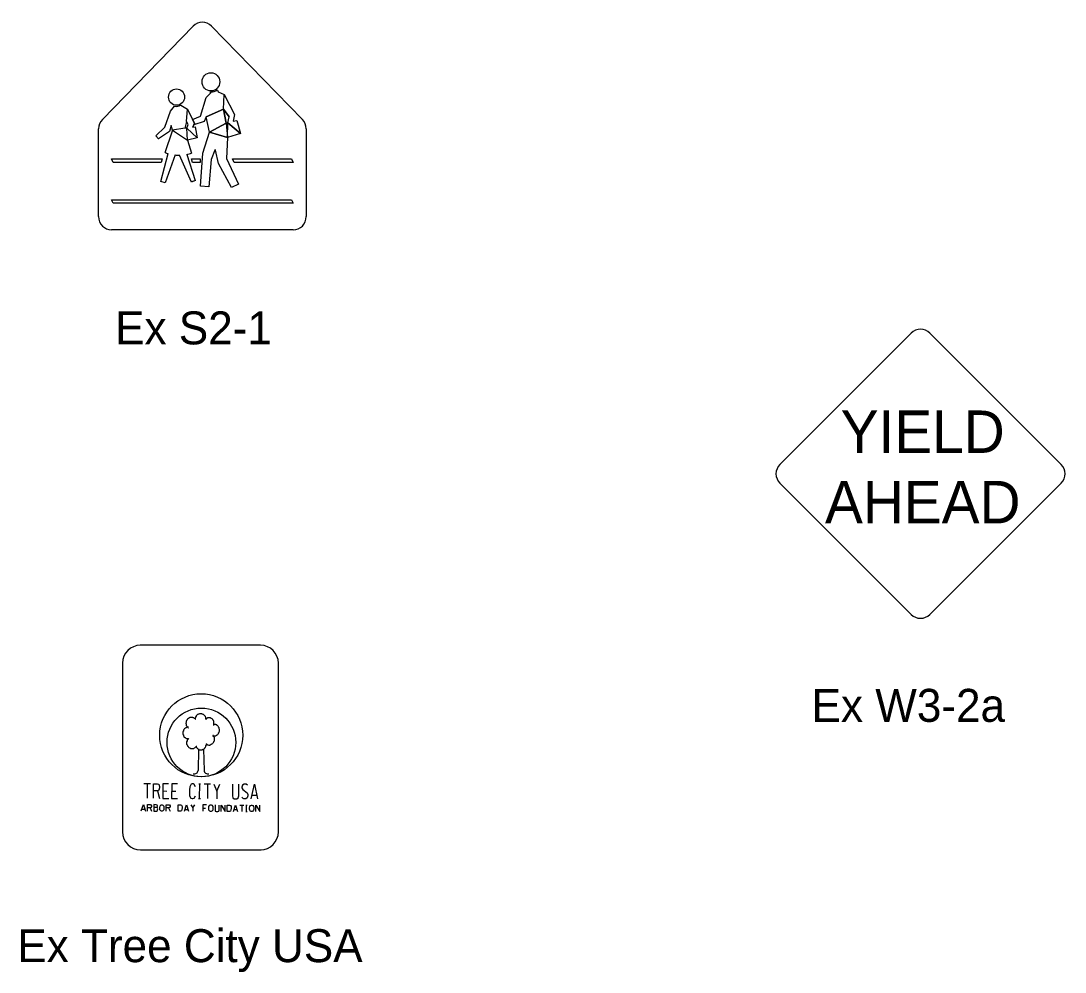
# Model space of a CAD drawing. Extents: x 42133 to 45533, y 41351 to 47951.
# Drawn here: x 43037.9 to 43275.5, y 46096.8 to 46313.2 of the extents above; entities that cross this region are included whole.
import ezdxf

# ---------------------------------------------------------------- set-up
doc = ezdxf.new("R2010")
doc.units = 0
doc.layers.add('P_TRAF_SIGN_SignDetails', color=7, linetype='Continuous')

msp = doc.modelspace()

# ---------------------------------------------------------------- linework, layer by layer
at = {"layer": 'P_TRAF_SIGN_SignDetails'}
for p, q in [((43056.47, 46290.82), (43077.12, 46312.05)), ((43081.31, 46312.05), (43101.97, 46290.82)), ((43082.56, 46297.55), (43082.65, 46297.49)), ((43078.78, 46291.58), (43080.06, 46295.78)), ((43080.06, 46295.78), (43081.05, 46296.76)), ((43081.07, 46297.06), (43081.05, 46296.76)), ((43081.05, 46296.76), (43081.07, 46297.06)), ((43082.65, 46297.49), (43082.78, 46297.06)), ((43082.78, 46297.06), (43084.14, 46296.52)), ((43084.04, 46293.17), (43084.14, 46296.52)), ((43084.14, 46296.52), (43086.48, 46291.93)), ((43071.92, 46292.73), (43072.87, 46293.83)), ((43071.92, 46292.73), (43072.87, 46293.83)), ((43074.29, 46294.03), (43075.83, 46293.16)), ((43074.29, 46294.03), (43075.83, 46293.16)), ((43075.56, 46290.37), (43075.83, 46293.16)), ((43077.39, 46289.95), (43075.83, 46293.16)), ((43077.39, 46289.95), (43075.83, 46293.16)), ((43075.83, 46293.16), (43077.39, 46289.95)), ((43075.83, 46293.16), (43077.39, 46289.95)), ((43075.9, 46293), (43075.9, 46293)), ((43084.04, 46293.17), (43080.09, 46291.38)), ((43080.09, 46291.38), (43084.04, 46293.17)), ((43085.27, 46291.39), (43084.04, 46293.17)), ((43084.61, 46289.95), (43084.04, 46293.17)), ((43084.04, 46293.17), (43085.27, 46291.39)), ((43085.27, 46291.39), (43084.04, 46293.17)), ((43084.04, 46293.17), (43084.61, 46289.95)), ((43085.27, 46291.39), (43084.04, 46293.17)), ((43084.04, 46293.17), (43084.61, 46289.95)), ((43070.7, 46289.06), (43071.92, 46292.73)), ((43070.7, 46289.06), (43071.92, 46292.73)), ((43075.56, 46290.37), (43075.19, 46288.82)), ((43075.96, 46289.69), (43075.56, 46290.37)), ((43076.06, 46292.67), (43076.06, 46292.67)), ((43076.23, 46292.33), (43076.23, 46292.33)), ((43076.39, 46292), (43076.39, 46292)), ((43076.55, 46291.66), (43076.55, 46291.66)), ((43076.72, 46291.33), (43076.72, 46291.33)), ((43076.88, 46290.99), (43076.88, 46290.99)), ((43076.99, 46290.77), (43078.78, 46291.58)), ((43080.09, 46291.38), (43079.59, 46290.34)), ((43080.81, 46287.92), (43080.09, 46291.38)), ((43084.97, 46290.04), (43085.27, 46291.39)), ((43084.97, 46290.04), (43085.27, 46291.39)), ((43086.48, 46291.93), (43086.22, 46290.43)), ((43086.22, 46290.43), (43087.01, 46290.59)), ((43087.01, 46290.59), (43087.88, 46287.59)), ((43055.59, 46268.7), (43055.59, 46288.68)), ((43068.62, 46287.09), (43070.7, 46289.06)), ((43068.62, 46287.09), (43070.7, 46289.06)), ((43071.71, 46288.06), (43069.23, 46286.42)), ((43071.71, 46288.06), (43069.23, 46286.42)), ((43070.76, 46283.29), (43072.37, 46288.18)), ((43070.76, 46283.29), (43072.37, 46288.18)), ((43072.09, 46289.46), (43071.71, 46288.06)), ((43072.09, 46289.46), (43071.71, 46288.06)), ((43072.39, 46288.36), (43072.09, 46289.46)), ((43072.39, 46288.36), (43072.09, 46289.46)), ((43072.37, 46288.18), (43072.39, 46288.36)), ((43072.37, 46288.18), (43072.39, 46288.36)), ((43075.19, 46288.82), (43072.39, 46288.36)), ((43075.19, 46288.82), (43072.39, 46288.36)), ((43072.39, 46288.36), (43075.81, 46286.12)), ((43072.39, 46288.36), (43075.81, 46286.12)), ((43075.64, 46288.84), (43075.19, 46288.82)), ((43075.64, 46288.84), (43075.96, 46289.69)), ((43078.01, 46286.65), (43075.64, 46288.84)), ((43075.81, 46286.12), (43075.64, 46288.84)), ((43075.64, 46288.84), (43078.01, 46286.65)), ((43077.39, 46289.95), (43077.07, 46289.02)), ((43077.07, 46289.02), (43077.39, 46289.95)), ((43077.39, 46289.95), (43077.07, 46289.02)), ((43077.39, 46289.95), (43077.07, 46289.02)), ((43077.07, 46289.02), (43077.55, 46289.11)), ((43077.07, 46289.02), (43077.55, 46289.11)), ((43079.59, 46290.34), (43077.25, 46289.56)), ((43077.28, 46289.65), (43077.28, 46289.65)), ((43077.28, 46289.65), (43077.28, 46289.65)), ((43077.55, 46289.11), (43078.01, 46286.65)), ((43077.55, 46289.11), (43078.01, 46286.65)), ((43084.61, 46289.95), (43080.81, 46287.92)), ((43084.97, 46290.04), (43084.61, 46289.95)), ((43084.61, 46289.95), (43084.95, 46286.73)), ((43084.95, 46286.73), (43084.97, 46290.04)), ((43084.95, 46286.73), (43084.97, 46290.04)), ((43087.88, 46287.59), (43084.97, 46290.04)), ((43084.97, 46290.04), (43087.88, 46287.59)), ((43102.82, 46288.68), (43102.82, 46268.7)), ((43069.23, 46286.42), (43068.62, 46287.09)), ((43069.23, 46286.42), (43068.62, 46287.09)), ((43069.17, 46286.49), (43069.33, 46286.49)), ((43078.01, 46286.65), (43075.81, 46286.12)), ((43078.01, 46286.65), (43075.81, 46286.12)), ((43075.81, 46286.12), (43076.76, 46283.13)), ((43075.81, 46286.12), (43076.76, 46283.13)), ((43079.28, 46283.13), (43080.81, 46287.92)), ((43084.95, 46286.73), (43080.81, 46287.92)), ((43080.81, 46287.92), (43084.95, 46286.73)), ((43080.81, 46287.92), (43084.95, 46286.73)), ((43084.95, 46286.73), (43080.81, 46287.92)), ((43084.95, 46286.73), (43080.81, 46287.92)), ((43080.81, 46287.92), (43084.95, 46286.73)), ((43080.81, 46287.92), (43084.95, 46286.73)), ((43084.95, 46286.73), (43080.81, 46287.92)), ((43084.95, 46286.73), (43080.81, 46287.92)), ((43080.81, 46287.92), (43084.95, 46286.73)), ((43084.95, 46286.73), (43084.71, 46281.9)), ((43087.88, 46287.59), (43084.95, 46286.73)), ((43082.02, 46283.83), (43081.21, 46281.73)), ((43082.89, 46280.79), (43082.18, 46283.83)), ((43058.55, 46281.85), (43070.06, 46281.85)), ((43058.93, 46281.04), (43058.55, 46281.85)), ((43069.86, 46281.04), (43058.93, 46281.04)), ((43069.78, 46276.68), (43071.4, 46283.03)), ((43069.78, 46276.68), (43071.4, 46283.03)), ((43070.06, 46281.85), (43069.86, 46281.04)), ((43073, 46282.74), (43070.72, 46276.39)), ((43073, 46282.74), (43070.72, 46276.39)), ((43076.72, 46276.54), (43074.01, 46282.69)), ((43076.72, 46276.54), (43074.01, 46282.69)), ((43075.65, 46282.86), (43077.58, 46276.88)), ((43075.65, 46282.86), (43077.58, 46276.88)), ((43076.74, 46281.85), (43078.71, 46281.85)), ((43076.99, 46281.04), (43076.74, 46281.85)), ((43078.71, 46281.04), (43076.99, 46281.04)), ((43078.71, 46281.85), (43078.71, 46281.04)), ((43078.81, 46275.63), (43079.28, 46283.13)), ((43081.21, 46281.73), (43080.65, 46275.49)), ((43084.71, 46281.9), (43087.43, 46276.11)), ((43086.08, 46281.85), (43099.5, 46281.85)), ((43086.46, 46281.04), (43086.08, 46281.85)), ((43099.88, 46281.04), (43086.46, 46281.04)), ((43099.5, 46281.85), (43099.88, 46281.04)), ((43085.81, 46275.33), (43082.89, 46280.79)), ((43070.72, 46276.39), (43069.78, 46276.68)), ((43070.72, 46276.39), (43069.78, 46276.68)), ((43077.61, 46276.94), (43076.72, 46276.59)), ((43077.61, 46276.94), (43076.72, 46276.59)), ((43077.58, 46276.88), (43076.72, 46276.54)), ((43080.65, 46275.49), (43078.81, 46275.63)), ((43087.43, 46276.11), (43085.81, 46275.33)), ((43058.55, 46272.54), (43099.5, 46272.54)), ((43058.93, 46271.73), (43058.55, 46272.54)), ((43099.88, 46271.73), (43058.93, 46271.73)), ((43099.5, 46272.54), (43099.88, 46271.73)), ((43099.88, 46265.67), (43058.55, 46265.67)), ((43210.6, 46212.29), (43240.49, 46242.18)), ((43244.74, 46242.18), (43274.62, 46212.29)), ((43240.49, 46178.16), (43210.61, 46208.04)), ((43274.62, 46208.04), (43244.74, 46178.16)), ((43092.44, 46171.15), (43065.08, 46171.15)), ((43061.04, 46167.09), (43061.04, 46128.63)), ((43096.5, 46128.64), (43096.5, 46167.21)), ((43078.22, 46142.67), (43078.21, 46142.65)), ((43079.58, 46142.67), (43079.59, 46142.65)), ((43065.12, 46124.58), (43092.61, 46124.58))]:
    msp.add_line(p, q, dxfattribs=at)
for points in [[(43077.25, 46289.56), (43077.39, 46289.95), (43076.99, 46290.77)], [(43080.81, 46287.92), (43084.61, 46289.95), (43084.95, 46286.73)], [(43080.02, 46154.3), (43080.02, 46154.41), (43080.02, 46154.51), (43080.02, 46154.73), (43079.91, 46154.84), (43079.91, 46154.95), (43079.8, 46155.05), (43079.69, 46155.16), (43079.59, 46155.26), (43079.48, 46155.37), (43079.37, 46155.37), (43079.27, 46155.48), (43079.16, 46155.48), (43079.05, 46155.58), (43078.95, 46155.58), (43078.84, 46155.58), (43078.62, 46155.58), (43078.52, 46155.58), (43078.41, 46155.48), (43078.3, 46155.48), (43078.2, 46155.37), (43078.09, 46155.37), (43077.98, 46155.26), (43077.87, 46155.16), (43077.77, 46155.05), (43077.77, 46154.95), (43077.66, 46154.84), (43077.66, 46154.73), (43077.55, 46154.51), (43077.55, 46154.41), (43077.55, 46154.3), (43077.66, 46154.3)], [(43077.66, 46154.3), (43077.55, 46154.41), (43077.45, 46154.51), (43077.34, 46154.51), (43077.23, 46154.62), (43077.12, 46154.62), (43077.02, 46154.73), (43076.8, 46154.73), (43076.7, 46154.73), (43076.59, 46154.73), (43076.48, 46154.73), (43076.38, 46154.73), (43076.27, 46154.62), (43076.05, 46154.51), (43075.95, 46154.51), (43075.84, 46154.41), (43075.84, 46154.3), (43075.73, 46154.19), (43075.63, 46154.08), (43075.63, 46153.98), (43075.52, 46153.87), (43075.52, 46153.76), (43075.52, 46153.55), (43075.41, 46153.44), (43075.41, 46153.34), (43075.52, 46153.23), (43075.52, 46153.02), (43075.52, 46152.91), (43075.63, 46152.8), (43075.73, 46152.69), (43075.73, 46152.59), (43075.84, 46152.48), (43075.95, 46152.37), (43075.95, 46152.37), (43076.05, 46152.37)], [(43081.84, 46152.91), (43081.84, 46153.02), (43081.84, 46153.12), (43081.84, 46153.23), (43081.84, 46153.44), (43081.84, 46153.55), (43081.84, 46153.66), (43081.84, 46153.76), (43081.84, 46153.87), (43081.73, 46153.98), (43081.73, 46154.08), (43081.62, 46154.19), (43081.52, 46154.3), (43081.41, 46154.41), (43081.3, 46154.51), (43081.2, 46154.51), (43081.09, 46154.62), (43080.98, 46154.62), (43080.87, 46154.62), (43080.77, 46154.62), (43080.66, 46154.62), (43080.55, 46154.62), (43080.34, 46154.62), (43080.23, 46154.51), (43080.12, 46154.51), (43080.02, 46154.41), (43080.02, 46154.3), (43080.12, 46154.3)], [(43081.52, 46150.55), (43081.62, 46150.55), (43081.73, 46150.55), (43081.84, 46150.55), (43082.05, 46150.55), (43082.16, 46150.55), (43082.27, 46150.55), (43082.37, 46150.66), (43082.48, 46150.66), (43082.59, 46150.76), (43082.7, 46150.87), (43082.8, 46150.98), (43082.91, 46151.09), (43082.91, 46151.2), (43083.02, 46151.3), (43083.02, 46151.41), (43083.12, 46151.62), (43083.12, 46151.73), (43083.12, 46151.84), (43083.12, 46151.94), (43083.02, 46152.16), (43083.02, 46152.26), (43083.02, 46152.37), (43082.91, 46152.48), (43082.91, 46152.59), (43082.8, 46152.69), (43082.7, 46152.8), (43082.59, 46152.91), (43082.48, 46153.02), (43082.37, 46153.02), (43082.27, 46153.12), (43082.05, 46153.12), (43081.95, 46153.12), (43081.84, 46153.12), (43081.73, 46153.12), (43081.73, 46153.12), (43081.84, 46153.12)], [(43076.05, 46152.48), (43075.95, 46152.48), (43075.84, 46152.48), (43075.73, 46152.48), (43075.52, 46152.37), (43075.41, 46152.37), (43075.3, 46152.26), (43075.2, 46152.16), (43075.09, 46152.16), (43075.09, 46152.05), (43074.98, 46151.94), (43074.88, 46151.84), (43074.88, 46151.62), (43074.77, 46151.52), (43074.77, 46151.41), (43074.77, 46151.3), (43074.77, 46151.09), (43074.77, 46150.98), (43074.77, 46150.87), (43074.88, 46150.76), (43074.88, 46150.55), (43074.98, 46150.44), (43074.98, 46150.34), (43075.09, 46150.23), (43075.2, 46150.12), (43075.3, 46150.12), (43075.41, 46150.02), (43075.52, 46149.91), (43075.63, 46149.91), (43075.73, 46149.91), (43075.95, 46149.91), (43075.95, 46149.91), (43076.05, 46149.91)], [(43080.02, 46148.73), (43080.12, 46148.62), (43080.23, 46148.62), (43080.34, 46148.52), (43080.44, 46148.52), (43080.66, 46148.41), (43080.77, 46148.41), (43080.87, 46148.41), (43080.98, 46148.52), (43081.09, 46148.52), (43081.2, 46148.62), (43081.3, 46148.62), (43081.41, 46148.73), (43081.52, 46148.84), (43081.62, 46148.84), (43081.73, 46149.05), (43081.84, 46149.16), (43081.84, 46149.27), (43081.95, 46149.37), (43081.95, 46149.48), (43081.95, 46149.59), (43081.95, 46149.8), (43081.95, 46149.91), (43081.95, 46150.02), (43081.95, 46150.23), (43081.84, 46150.34), (43081.84, 46150.44), (43081.73, 46150.55), (43081.62, 46150.66), (43081.73, 46150.66)], [(43076.05, 46149.91), (43075.95, 46149.8), (43075.84, 46149.7), (43075.84, 46149.59), (43075.73, 46149.48), (43075.73, 46149.37), (43075.63, 46149.16), (43075.63, 46149.05), (43075.63, 46148.94), (43075.63, 46148.84), (43075.63, 46148.62), (43075.73, 46148.52), (43075.73, 46148.41), (43075.84, 46148.3), (43075.84, 46148.2), (43075.95, 46148.09), (43076.05, 46147.98), (43076.16, 46147.88), (43076.27, 46147.77), (43076.38, 46147.77), (43076.48, 46147.66), (43076.59, 46147.66), (43076.7, 46147.66), (43076.91, 46147.66), (43077.02, 46147.66), (43077.12, 46147.66), (43077.23, 46147.66), (43077.34, 46147.77), (43077.45, 46147.77), (43077.55, 46147.88), (43077.66, 46147.98), (43077.77, 46148.09), (43077.87, 46148.2), (43077.98, 46148.2)], [(43077.77, 46148.09), (43077.87, 46147.98), (43077.87, 46147.88), (43077.98, 46147.77), (43078.09, 46147.66), (43078.2, 46147.55), (43078.3, 46147.55), (43078.41, 46147.45), (43078.52, 46147.34), (43078.62, 46147.34), (43078.73, 46147.34), (43078.95, 46147.34), (43079.05, 46147.34), (43079.16, 46147.34), (43079.27, 46147.45), (43079.37, 46147.45), (43079.48, 46147.55), (43079.59, 46147.55), (43079.69, 46147.66), (43079.8, 46147.77), (43079.91, 46147.88), (43079.91, 46147.98), (43080.02, 46148.09), (43080.02, 46148.3), (43080.12, 46148.41), (43080.12, 46148.52), (43080.12, 46148.62), (43080.12, 46148.73), (43080.23, 46148.73)], [(43078.36, 46147.53), (43078.22, 46142.67)], [(43079.44, 46147.5), (43079.58, 46142.67)], [(43065.91, 46139.67), (43067.37, 46139.66)], [(43066.65, 46139.66), (43066.63, 46136.33)], [(43068.08, 46136.32), (43068.1, 46139.65), (43069, 46139.65), (43069.26, 46139.51), (43069.48, 46138.99), (43069.48, 46138.67), (43069.27, 46138.15), (43068.99, 46138.02), (43068.09, 46138.02)], [(43071.5, 46139.63), (43070.22, 46139.64), (43070.2, 46136.31), (43071.57, 46136.3)], [(43073.51, 46139.62), (43072.23, 46139.63), (43072.21, 46136.29), (43073.58, 46136.29)], [(43077.64, 46138.94), (43077.36, 46139.49), (43077.08, 46139.6), (43076.89, 46139.6), (43076.63, 46139.5), (43076.33, 46138.95), (43076.25, 46138.21), (43076.25, 46137.82), (43076.25, 46137.56), (43076.26, 46137.32), (43076.31, 46136.9), (43076.61, 46136.37), (43076.87, 46136.27), (43077.03, 46136.27), (43077.33, 46136.37), (43077.63, 46136.89)], [(43078.38, 46139.59), (43078.8, 46139.59)], [(43078.57, 46136.26), (43078.59, 46139.59)], [(43079.62, 46139.59), (43081.07, 46139.58)], [(43080.36, 46139.58), (43080.34, 46136.25)], [(43081.81, 46139.57), (43082.5, 46137.97), (43083.21, 46139.57)], [(43086.08, 46139.55), (43086.06, 46136.9), (43086.13, 46136.42), (43086.45, 46136.21), (43087.04, 46136.21), (43087.36, 46136.42), (43087.47, 46136.89), (43087.48, 46139.54)], [(43089.49, 46139.29), (43089.14, 46139.53), (43088.74, 46139.53), (43088.37, 46139.3), (43088.21, 46138.88), (43088.21, 46138.72), (43088.38, 46138.33), (43089.39, 46137.53), (43089.57, 46137.17), (43089.55, 46136.85), (43089.39, 46136.43), (43089.09, 46136.2), (43088.67, 46136.2), (43088.48, 46136.3), (43088.2, 46136.6)], [(43090.3, 46136.19), (43091.05, 46139.52), (43091.75, 46136.18)], [(43068.97, 46138.02), (43069.47, 46136.31)], [(43070.21, 46137.99), (43071.12, 46137.98)], [(43072.22, 46137.97), (43073.13, 46137.97)], [(43078.36, 46136.26), (43078.78, 46136.26)], [(43082.5, 46137.97), (43082.49, 46136.23)], [(43091.58, 46136.97), (43090.48, 46136.98)], [(43065.31, 46133.44), (43065.8, 46134.89), (43066.26, 46133.43)], [(43066.15, 46133.78), (43065.43, 46133.78)], [(43066.74, 46133.43), (43066.75, 46134.88), (43067.33, 46134.88), (43067.51, 46134.82), (43067.65, 46134.59), (43067.65, 46134.46), (43067.51, 46134.23), (43067.33, 46134.17), (43066.75, 46134.17)], [(43067.32, 46134.17), (43067.65, 46133.42)], [(43068.79, 46134.21), (43068.91, 46134.35), (43068.97, 46134.52), (43068.97, 46134.57), (43068.91, 46134.77), (43068.72, 46134.87), (43068.14, 46134.88), (43068.13, 46133.42), (43068.78, 46133.42), (43068.96, 46133.52), (43069.03, 46133.71), (43069.04, 46133.89), (43068.97, 46134.06), (43068.79, 46134.21), (43068.13, 46134.21)], [(43069.93, 46134.87), (43070.05, 46134.87), (43070.24, 46134.78), (43070.43, 46134.54), (43070.47, 46134.26), (43070.47, 46133.99), (43070.42, 46133.71), (43070.22, 46133.47), (43070.04, 46133.41), (43069.93, 46133.41), (43069.76, 46133.47), (43069.56, 46133.71), (43069.52, 46134), (43069.52, 46134.26), (43069.57, 46134.56), (43069.76, 46134.8), (43069.93, 46134.87)], [(43070.95, 46133.41), (43070.95, 46134.86), (43071.54, 46134.86), (43071.71, 46134.8), (43071.86, 46134.57), (43071.86, 46134.43), (43071.72, 46134.2), (43071.53, 46134.15), (43070.95, 46134.15)], [(43071.52, 46134.15), (43071.85, 46133.4)], [(43073.73, 46134.84), (43074.25, 46134.84), (43074.45, 46134.74), (43074.57, 46134.48), (43074.63, 46134.15), (43074.56, 46133.74), (43074.43, 46133.49), (43074.25, 46133.39), (43073.72, 46133.39), (43073.73, 46134.84)], [(43075.11, 46133.38), (43075.59, 46134.83), (43076.06, 46133.38)], [(43075.94, 46133.72), (43075.22, 46133.72)], [(43076.55, 46134.83), (43077, 46134.13), (43077.46, 46134.82)], [(43077, 46134.13), (43077, 46133.37)], [(43080.18, 46134.81), (43079.34, 46134.81), (43079.33, 46133.36)], [(43079.34, 46134.1), (43079.93, 46134.1)], [(43081.07, 46134.8), (43081.19, 46134.8), (43081.38, 46134.72), (43081.56, 46134.48), (43081.61, 46134.19), (43081.61, 46133.93), (43081.56, 46133.64), (43081.36, 46133.4), (43081.18, 46133.35), (43081.06, 46133.35), (43080.89, 46133.41), (43080.7, 46133.65), (43080.65, 46133.93), (43080.66, 46134.2), (43080.7, 46134.49), (43080.9, 46134.73), (43081.07, 46134.8)], [(43082.09, 46134.8), (43082.08, 46133.64), (43082.13, 46133.43), (43082.34, 46133.34), (43082.72, 46133.34), (43082.93, 46133.43), (43083, 46133.63), (43083.01, 46134.79)], [(43083.48, 46133.33), (43083.49, 46134.79), (43084.39, 46133.33), (43084.39, 46134.78)], [(43084.88, 46134.78), (43085.4, 46134.78), (43085.6, 46134.67), (43085.72, 46134.42), (43085.78, 46134.09), (43085.71, 46133.68), (43085.58, 46133.42), (43085.39, 46133.32), (43084.87, 46133.32), (43084.88, 46134.78)], [(43086.25, 46133.32), (43086.74, 46134.77), (43087.2, 46133.31)], [(43087.09, 46133.66), (43086.37, 46133.66)], [(43087.69, 46134.76), (43088.65, 46134.76)], [(43088.18, 46134.76), (43088.17, 46133.31)], [(43089.13, 46134.76), (43089.4, 46134.75)], [(43089.26, 46133.3), (43089.26, 46134.75)], [(43090.35, 46134.75), (43090.47, 46134.75), (43090.66, 46134.67), (43090.84, 46134.42), (43090.89, 46134.14), (43090.89, 46133.87), (43090.84, 46133.59), (43090.64, 46133.35), (43090.46, 46133.29), (43090.34, 46133.29), (43090.17, 46133.35), (43089.98, 46133.59), (43089.94, 46133.88), (43089.94, 46134.14), (43089.98, 46134.44), (43090.18, 46134.68), (43090.35, 46134.75)], [(43091.36, 46133.29), (43091.37, 46134.74), (43092.27, 46133.28), (43092.28, 46134.74)], [(43089.12, 46133.3), (43089.39, 46133.3)]]:
    msp.add_lwpolyline(points, dxfattribs=at)
for centre, radius in [((43078.94, 46150.66), 9.45), ((43078.99, 46149.04), 7.81)]:
    msp.add_circle(centre, radius, dxfattribs=at)
for centre, radius, start, end in [((43242.61, 46240.05), 3.01, 45.0123, 135), ((43242.61, 46240.05), 3.01, 45.0123, 135), ((43212.73, 46210.17), 3.01, 135, 225.0172), ((43272.49, 46210.17), 3.01, 315, 44.9762), ((43242.61, 46180.29), 3.01, 224.9829, 315), ((43065.14, 46167.05), 4.1, 90, 180), ((43092.4, 46167.05), 4.1, 360, 90), ((43077.38, 46142.72), 0.837, 252.3511, 355.5975), ((43080.42, 46142.72), 0.837, 184.4025, 287.6489), ((43065.14, 46128.68), 4.1, 180, 270), ((43092.4, 46128.68), 4.1, 270, 0)]:
    msp.add_arc(centre, radius, start, end, dxfattribs=at)
for centre, major_axis, start_param, end_param in [((43079.21, 46309.91), (0, 3.03), 5.49782, 7.068583), ((43081.3, 46298.98), (0, -1.93), 6.157517, 7.020334), ((43073.29, 46296.09), (0, -2.31), 6.095326, 6.744556), ((43073.29, 46296.09), (0, -2.31), 6.095326, 6.744556), ((43058.55, 46288.68), (0, -3.03), 3.926991, 4.712389), ((43099.88, 46288.68), (0, 3.03), 4.712389, 5.49775), ((43071.65, 46284.68), (0, -1.66), 5.703441, 6.132872), ((43071.65, 46284.68), (0, -1.66), 5.703441, 6.132872), ((43082.1, 46283.81), (0, 0.0872), 5.046905, 7.52285), ((43073.65, 46285.97), (0, -3.29), 6.078852, 6.394937), ((43073.65, 46285.97), (0, -3.29), 6.078852, 6.394937), ((43075.35, 46286.59), (0, -3.74), 0.083253, 0.393979), ((43075.35, 46286.59), (0, -3.74), 0.083253, 0.393979), ((43058.55, 46268.7), (0, -3.03), 4.712389, 6.283185), ((43099.88, 46268.7), (0, 3.03), 3.141593, 4.712389)]:
    msp.add_ellipse(centre, major_axis=major_axis, ratio=0.9732, start_param=start_param, end_param=end_param, dxfattribs=at)
for centre, major_axis in [((43081.15, 46299.37), (0, 2.08)), ((43073.32, 46295.89), (0, 1.87))]:
    msp.add_ellipse(centre, major_axis=major_axis, ratio=0.9732, dxfattribs=at)

# ---------------------------------------------------------------- texts
for s, height, p in [('Ex S2-1', 7.5, (43059.35, 46239.62)), ('YIELD', 9.656, (43224.44, 46214.92)), ('AHEAD', 9.656, (43220.87, 46198.9)), ('Ex W3-2a', 7.5, (43217.81, 46153.72)), ('Ex Tree City USA', 7.5, (43037.09, 46099.03))]:
    msp.add_text(s, height=height, dxfattribs=at).set_placement(p)

doc.saveas('drawing.dxf')
